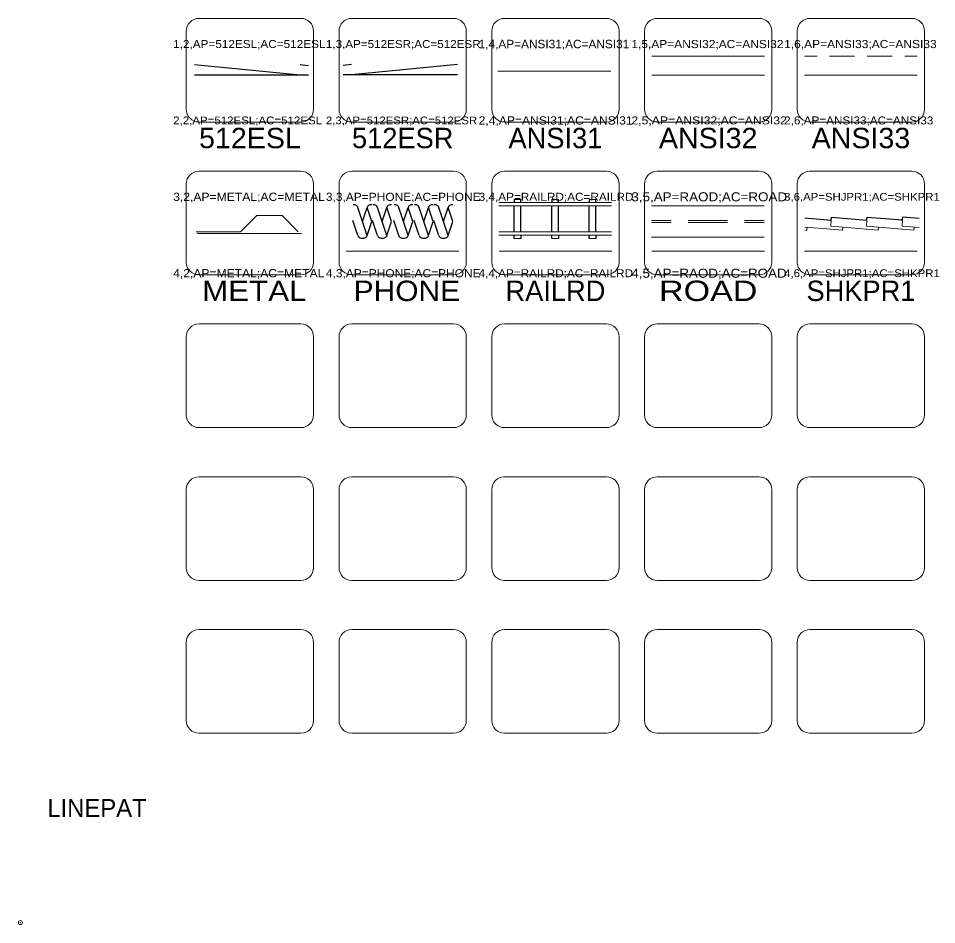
# Model space of a CAD drawing. Extents: x 95935 to 95946.4, y 95971.2 to 95974.7.
# Drawn here: x 95935.026 to 95938.633, y 95971.173 to 95974.732 of the extents above; entities that cross this region are included whole.
import ezdxf
from ezdxf.enums import TextEntityAlignment as Align

# ---------------------------------------------------------------- set-up
doc = ezdxf.new("R2010")
doc.units = 0
doc.header["$LTSCALE"] = 0.032
doc.header["$PDMODE"] = 32
doc.header["$PDSIZE"] = 0.016
for name, color, linetype, lineweight in [('1', 7, 'Continuous', 13), ('25', 7, 'Continuous', 13), ('6', 7, 'Continuous', 13), ('63', 7, 'Continuous', 13)]:
    doc.layers.add(name, color=color, linetype=linetype, lineweight=lineweight)
doc.layers.add('20', color=7, linetype='Continuous')

msp = doc.modelspace()

# ---------------------------------------------------------------- linework, layer by layer
at = {"layer": '1'}
for p, q in [((95935.7357, 95974.7318), (95936.1357, 95974.7318)), ((95936.3357, 95974.7318), (95936.7357, 95974.7318)), ((95936.9357, 95974.7318), (95937.3357, 95974.7318)), ((95937.5357, 95974.7318), (95937.9357, 95974.7318)), ((95938.1357, 95974.7318), (95938.5357, 95974.7318)), ((95935.6857, 95974.3747), (95935.6857, 95974.6818)), ((95936.1857, 95974.6818), (95936.1857, 95974.3747)), ((95936.2857, 95974.3747), (95936.2857, 95974.6818)), ((95936.7857, 95974.6818), (95936.7857, 95974.3747)), ((95936.8857, 95974.3747), (95936.8857, 95974.6818)), ((95937.3857, 95974.6818), (95937.3857, 95974.3747)), ((95937.4857, 95974.3747), (95937.4857, 95974.6818)), ((95937.9857, 95974.6818), (95937.9857, 95974.3747)), ((95938.0857, 95974.3747), (95938.0857, 95974.6818)), ((95938.5857, 95974.6818), (95938.5857, 95974.3747)), ((95936.1357, 95974.3247), (95935.7357, 95974.3247)), ((95936.7357, 95974.3247), (95936.3357, 95974.3247)), ((95937.3357, 95974.3247), (95936.9357, 95974.3247)), ((95937.9357, 95974.3247), (95937.5357, 95974.3247)), ((95938.5357, 95974.3247), (95938.1357, 95974.3247)), ((95935.7357, 95974.1318), (95936.1357, 95974.1318)), ((95936.3357, 95974.1318), (95936.7357, 95974.1318)), ((95936.9357, 95974.1318), (95937.3357, 95974.1318)), ((95937.5357, 95974.1318), (95937.9357, 95974.1318)), ((95938.1357, 95974.1318), (95938.5357, 95974.1318)), ((95935.6857, 95973.7747), (95935.6857, 95974.0818)), ((95936.1857, 95974.0818), (95936.1857, 95973.7747)), ((95936.2857, 95973.7747), (95936.2857, 95974.0818)), ((95936.7857, 95974.0818), (95936.7857, 95973.7747)), ((95936.8857, 95973.7747), (95936.8857, 95974.0818)), ((95937.3857, 95974.0818), (95937.3857, 95973.7747)), ((95937.4857, 95973.7747), (95937.4857, 95974.0818)), ((95937.9857, 95974.0818), (95937.9857, 95973.7747)), ((95938.0857, 95973.7747), (95938.0857, 95974.0818)), ((95938.5857, 95974.0818), (95938.5857, 95973.7747)), ((95936.1357, 95973.7247), (95935.7357, 95973.7247)), ((95936.7357, 95973.7247), (95936.3357, 95973.7247)), ((95937.3357, 95973.7247), (95936.9357, 95973.7247)), ((95937.9357, 95973.7247), (95937.5357, 95973.7247)), ((95938.5357, 95973.7247), (95938.1357, 95973.7247)), ((95935.7357, 95973.5318), (95936.1357, 95973.5318)), ((95936.3357, 95973.5318), (95936.7357, 95973.5318)), ((95936.9357, 95973.5318), (95937.3357, 95973.5318)), ((95937.5357, 95973.5318), (95937.9357, 95973.5318)), ((95938.1357, 95973.5318), (95938.5357, 95973.5318)), ((95935.6857, 95973.1747), (95935.6857, 95973.4818)), ((95936.1857, 95973.4818), (95936.1857, 95973.1747)), ((95936.2857, 95973.1747), (95936.2857, 95973.4818)), ((95936.7857, 95973.4818), (95936.7857, 95973.1747)), ((95936.8857, 95973.1747), (95936.8857, 95973.4818)), ((95937.3857, 95973.4818), (95937.3857, 95973.1747)), ((95937.4857, 95973.1747), (95937.4857, 95973.4818)), ((95937.9857, 95973.4818), (95937.9857, 95973.1747)), ((95938.0857, 95973.1747), (95938.0857, 95973.4818)), ((95938.5857, 95973.4818), (95938.5857, 95973.1747)), ((95936.1357, 95973.1247), (95935.7357, 95973.1247)), ((95936.7357, 95973.1247), (95936.3357, 95973.1247)), ((95937.3357, 95973.1247), (95936.9357, 95973.1247)), ((95937.9357, 95973.1247), (95937.5357, 95973.1247)), ((95938.5357, 95973.1247), (95938.1357, 95973.1247)), ((95935.7357, 95972.9318), (95936.1357, 95972.9318)), ((95936.3357, 95972.9318), (95936.7357, 95972.9318)), ((95936.9357, 95972.9318), (95937.3357, 95972.9318)), ((95937.5357, 95972.9318), (95937.9357, 95972.9318)), ((95938.1357, 95972.9318), (95938.5357, 95972.9318)), ((95935.6857, 95972.5747), (95935.6857, 95972.8818)), ((95936.1857, 95972.8818), (95936.1857, 95972.5747)), ((95936.2857, 95972.5747), (95936.2857, 95972.8818)), ((95936.7857, 95972.8818), (95936.7857, 95972.5747)), ((95936.8857, 95972.5747), (95936.8857, 95972.8818)), ((95937.3857, 95972.8818), (95937.3857, 95972.5747)), ((95937.4857, 95972.5747), (95937.4857, 95972.8818)), ((95937.9857, 95972.8818), (95937.9857, 95972.5747)), ((95938.0857, 95972.5747), (95938.0857, 95972.8818)), ((95938.5857, 95972.8818), (95938.5857, 95972.5747)), ((95936.1357, 95972.5247), (95935.7357, 95972.5247)), ((95936.7357, 95972.5247), (95936.3357, 95972.5247)), ((95937.3357, 95972.5247), (95936.9357, 95972.5247)), ((95937.9357, 95972.5247), (95937.5357, 95972.5247)), ((95938.5357, 95972.5247), (95938.1357, 95972.5247)), ((95935.7357, 95972.3318), (95936.1357, 95972.3318)), ((95936.3357, 95972.3318), (95936.7357, 95972.3318)), ((95936.9357, 95972.3318), (95937.3357, 95972.3318)), ((95937.5357, 95972.3318), (95937.9357, 95972.3318)), ((95938.1357, 95972.3318), (95938.5357, 95972.3318)), ((95935.6857, 95971.9747), (95935.6857, 95972.2818)), ((95936.1857, 95972.2818), (95936.1857, 95971.9747)), ((95936.2857, 95971.9747), (95936.2857, 95972.2818)), ((95936.7857, 95972.2818), (95936.7857, 95971.9747)), ((95936.8857, 95971.9747), (95936.8857, 95972.2818)), ((95937.3857, 95972.2818), (95937.3857, 95971.9747)), ((95937.4857, 95971.9747), (95937.4857, 95972.2818)), ((95937.9857, 95972.2818), (95937.9857, 95971.9747)), ((95938.0857, 95971.9747), (95938.0857, 95972.2818)), ((95938.5857, 95972.2818), (95938.5857, 95971.9747)), ((95936.1357, 95971.9247), (95935.7357, 95971.9247)), ((95936.7357, 95971.9247), (95936.3357, 95971.9247)), ((95937.3357, 95971.9247), (95936.9357, 95971.9247)), ((95937.9357, 95971.9247), (95937.5357, 95971.9247)), ((95938.5357, 95971.9247), (95938.1357, 95971.9247))]:
    msp.add_line(p, q, dxfattribs=at)
for centre, start, end in [((95935.7357, 95974.6818), 90, 180), ((95936.1357, 95974.6818), 0, 90), ((95936.3357, 95974.6818), 90, 180), ((95936.7357, 95974.6818), 0, 90), ((95936.9357, 95974.6818), 90, 180), ((95937.3357, 95974.6818), 0, 90), ((95937.5357, 95974.6818), 90, 180), ((95937.9357, 95974.6818), 0, 90), ((95938.1357, 95974.6818), 90, 180), ((95938.5357, 95974.6818), 0, 90), ((95935.7357, 95974.3747), 180, 270), ((95936.1357, 95974.3747), 270, 0), ((95936.3357, 95974.3747), 180, 270), ((95936.7357, 95974.3747), 270, 0), ((95936.9357, 95974.3747), 180, 270), ((95937.3357, 95974.3747), 270, 0), ((95937.5357, 95974.3747), 180, 270), ((95937.9357, 95974.3747), 270, 0), ((95938.1357, 95974.3747), 180, 270), ((95938.5357, 95974.3747), 270, 0), ((95935.7357, 95974.0818), 90, 180), ((95936.1357, 95974.0818), 0, 90), ((95936.3357, 95974.0818), 90, 180), ((95936.7357, 95974.0818), 0, 90), ((95936.9357, 95974.0818), 90, 180), ((95937.3357, 95974.0818), 0, 90), ((95937.5357, 95974.0818), 90, 180), ((95937.9357, 95974.0818), 0, 90), ((95938.1357, 95974.0818), 90, 180), ((95938.5357, 95974.0818), 0, 90), ((95935.7357, 95973.7747), 180, 270), ((95936.1357, 95973.7747), 270, 0), ((95936.3357, 95973.7747), 180, 270), ((95936.7357, 95973.7747), 270, 0), ((95936.9357, 95973.7747), 180, 270), ((95937.3357, 95973.7747), 270, 0), ((95937.5357, 95973.7747), 180, 270), ((95937.9357, 95973.7747), 270, 0), ((95938.1357, 95973.7747), 180, 270), ((95938.5357, 95973.7747), 270, 0), ((95935.7357, 95973.4818), 90, 180), ((95936.1357, 95973.4818), 0, 90), ((95936.3357, 95973.4818), 90, 180), ((95936.7357, 95973.4818), 0, 90), ((95936.9357, 95973.4818), 90, 180), ((95937.3357, 95973.4818), 0, 90), ((95937.5357, 95973.4818), 90, 180), ((95937.9357, 95973.4818), 0, 90), ((95938.1357, 95973.4818), 90, 180), ((95938.5357, 95973.4818), 0, 90), ((95935.7357, 95973.1747), 180, 270), ((95936.1357, 95973.1747), 270, 0), ((95936.3357, 95973.1747), 180, 270), ((95936.7357, 95973.1747), 270, 0), ((95936.9357, 95973.1747), 180, 270), ((95937.3357, 95973.1747), 270, 0), ((95937.5357, 95973.1747), 180, 270), ((95937.9357, 95973.1747), 270, 0), ((95938.1357, 95973.1747), 180, 270), ((95938.5357, 95973.1747), 270, 0), ((95935.7357, 95972.8818), 90, 180), ((95936.1357, 95972.8818), 0, 90), ((95936.3357, 95972.8818), 90, 180), ((95936.7357, 95972.8818), 0, 90), ((95936.9357, 95972.8818), 90, 180), ((95937.3357, 95972.8818), 0, 90), ((95937.5357, 95972.8818), 90, 180), ((95937.9357, 95972.8818), 0, 90), ((95938.1357, 95972.8818), 90, 180), ((95938.5357, 95972.8818), 0, 90), ((95935.7357, 95972.5747), 180, 270), ((95936.1357, 95972.5747), 270, 0), ((95936.3357, 95972.5747), 180, 270), ((95936.7357, 95972.5747), 270, 0), ((95936.9357, 95972.5747), 180, 270), ((95937.3357, 95972.5747), 270, 0), ((95937.5357, 95972.5747), 180, 270), ((95937.9357, 95972.5747), 270, 0), ((95938.1357, 95972.5747), 180, 270), ((95938.5357, 95972.5747), 270, 0), ((95935.7357, 95972.2818), 90, 180), ((95936.1357, 95972.2818), 0, 90), ((95936.3357, 95972.2818), 90, 180), ((95936.7357, 95972.2818), 0, 90), ((95936.9357, 95972.2818), 90, 180), ((95937.3357, 95972.2818), 0, 90), ((95937.5357, 95972.2818), 90, 180), ((95937.9357, 95972.2818), 0, 90), ((95938.1357, 95972.2818), 90, 180), ((95938.5357, 95972.2818), 0, 90), ((95935.7357, 95971.9747), 180, 270), ((95936.1357, 95971.9747), 270, 0), ((95936.3357, 95971.9747), 180, 270), ((95936.7357, 95971.9747), 270, 0), ((95936.9357, 95971.9747), 180, 270), ((95937.3357, 95971.9747), 270, 0), ((95937.5357, 95971.9747), 180, 270), ((95937.9357, 95971.9747), 270, 0), ((95938.1357, 95971.9747), 180, 270), ((95938.5357, 95971.9747), 270, 0)]:
    msp.add_arc(centre, 0.05, start, end, dxfattribs=at)
at = {"layer": '25'}
for p, q in [((95935.7278, 95973.8875), (95936.1378, 95973.8875)), ((95937.3569, 95973.8178), (95936.9141, 95973.8178)), ((95937.9569, 95973.8178), (95937.5141, 95973.8178)), ((95938.5569, 95973.8178), (95938.1141, 95973.8178))]:
    msp.add_line(p, q, dxfattribs=at)
at = {"layer": '6'}
for p, q in [((95937.5141, 95974.5836), (95937.9569, 95974.5836)), ((95938.1141, 95974.5836), (95938.1633, 95974.5836)), ((95938.2125, 95974.5836), (95938.3109, 95974.5836)), ((95938.3601, 95974.5836), (95938.4585, 95974.5836)), ((95938.5077, 95974.5836), (95938.5569, 95974.5836)), ((95936.9101, 95974.5244), (95937.3529, 95974.5244)), ((95937.5141, 95974.5086), (95937.9569, 95974.5086)), ((95938.1141, 95974.5086), (95938.5569, 95974.5086)), ((95936.9128, 95974.0083), (95937.3556, 95974.0083)), ((95936.9128, 95973.9955), (95937.3556, 95973.9955)), ((95936.9736, 95974.021), (95936.9999, 95974.021)), ((95937.1212, 95974.021), (95937.1475, 95974.021)), ((95937.2688, 95974.021), (95937.2951, 95974.021)), ((95937.5127, 95973.9951), (95937.9555, 95973.9951)), ((95937.5127, 95973.9375), (95937.5902, 95973.9375)), ((95937.5127, 95973.9299), (95937.5902, 95973.9299)), ((95937.6566, 95973.9375), (95937.8116, 95973.9375)), ((95937.6566, 95973.9299), (95937.8116, 95973.9299)), ((95937.878, 95973.9375), (95937.9555, 95973.9375)), ((95937.878, 95973.9299), (95937.9555, 95973.9299)), ((95938.2192, 95973.9395), (95938.2172, 95973.9155)), ((95938.3592, 95973.9398), (95938.3572, 95973.9158)), ((95938.4992, 95973.9401), (95938.4972, 95973.9161)), ((95936.9128, 95973.8931), (95937.3556, 95973.8931)), ((95938.1154, 95973.912), (95938.2192, 95973.9034)), ((95938.1154, 95973.9001), (95938.1239, 95973.8994)), ((95938.1249, 95973.9113), (95938.1239, 95973.8994)), ((95938.2152, 95973.9037), (95938.2639, 95973.8997)), ((95938.2172, 95973.9155), (95938.3592, 95973.9037)), ((95938.2649, 95973.9116), (95938.2639, 95973.8997)), ((95938.3552, 95973.904), (95938.4039, 95973.9)), ((95938.3572, 95973.9158), (95938.4992, 95973.904)), ((95938.4049, 95973.9119), (95938.4039, 95973.9)), ((95938.4952, 95973.9043), (95938.5439, 95973.9003)), ((95938.4972, 95973.9161), (95938.5641, 95973.9105)), ((95938.5449, 95973.9122), (95938.5439, 95973.9003)), ((95936.9128, 95973.8803), (95937.3556, 95973.8803)), ((95936.9736, 95973.8675), (95936.9999, 95973.8675)), ((95937.1212, 95973.8675), (95937.1475, 95973.8675)), ((95937.2688, 95973.8675), (95937.2951, 95973.8675)), ((95937.5127, 95973.8723), (95937.9555, 95973.8723))]:
    msp.add_line(p, q, dxfattribs=at)
at = {"layer": '6', "lineweight": 25}
for p, q in [((95935.7175, 95974.5504), (95936.1335, 95974.5104)), ((95936.1335, 95974.5504), (95936.1663, 95974.5472)), ((95936.3347, 95974.5504), (95936.3019, 95974.5472)), ((95936.7507, 95974.5504), (95936.3347, 95974.5104)), ((95935.7175, 95974.5104), (95936.1663, 95974.5104)), ((95936.7507, 95974.5104), (95936.3019, 95974.5104)), ((95936.9736, 95974.021), (95936.9736, 95974.0082)), ((95936.9736, 95973.8931), (95936.9736, 95973.9955)), ((95936.9999, 95974.0082), (95936.9999, 95974.021)), ((95936.9999, 95973.8931), (95936.9999, 95973.9955)), ((95937.1212, 95974.021), (95937.1212, 95974.0082)), ((95937.1212, 95973.8931), (95937.1212, 95973.9955)), ((95937.1475, 95974.0082), (95937.1475, 95974.021)), ((95937.1475, 95973.8931), (95937.1475, 95973.9955)), ((95937.2688, 95974.021), (95937.2688, 95974.0082)), ((95937.2688, 95973.8931), (95937.2688, 95973.9955)), ((95937.2951, 95974.0082), (95937.2951, 95974.021)), ((95937.2951, 95973.8931), (95937.2951, 95973.9955)), ((95936.3961, 95973.8798), (95936.3596, 95973.9895)), ((95936.3779, 95973.9346), (95936.3961, 95973.9892)), ((95936.4144, 95973.9345), (95936.3961, 95973.9895)), ((95936.4735, 95973.8798), (95936.437, 95973.9895)), ((95936.4553, 95973.9346), (95936.4735, 95973.9892)), ((95936.4918, 95973.9345), (95936.4735, 95973.9895)), ((95936.5568, 95973.8798), (95936.5203, 95973.9895)), ((95936.5386, 95973.9346), (95936.5568, 95973.9892)), ((95936.5751, 95973.9345), (95936.5568, 95973.9895)), ((95936.6372, 95973.8798), (95936.6007, 95973.9895)), ((95936.619, 95973.9346), (95936.6372, 95973.9892)), ((95936.6555, 95973.9345), (95936.6372, 95973.9895)), ((95936.7145, 95973.8798), (95936.678, 95973.9895)), ((95936.6963, 95973.9346), (95936.7145, 95973.9892)), ((95936.7328, 95973.9345), (95936.7145, 95973.9895)), ((95936.3596, 95973.8798), (95936.3403, 95973.9378)), ((95936.3961, 95973.8798), (95936.4143, 95973.9345)), ((95936.437, 95973.8798), (95936.4177, 95973.9378)), ((95936.4735, 95973.8798), (95936.4917, 95973.9345)), ((95936.5203, 95973.8798), (95936.501, 95973.9378)), ((95936.5568, 95973.8798), (95936.575, 95973.9345)), ((95936.6007, 95973.8798), (95936.5814, 95973.9378)), ((95936.6372, 95973.8798), (95936.6554, 95973.9345)), ((95936.678, 95973.8798), (95936.6587, 95973.9378)), ((95936.7145, 95973.8798), (95936.7327, 95973.9345)), ((95938.1154, 95973.9482), (95938.2192, 95973.9395)), ((95938.2152, 95973.9398), (95938.2192, 95973.9395)), ((95938.2192, 95973.9395), (95938.2202, 95973.9514)), ((95938.2202, 95973.9514), (95938.3592, 95973.9398)), ((95938.3552, 95973.9401), (95938.3592, 95973.9398)), ((95938.3592, 95973.9398), (95938.3602, 95973.9517)), ((95938.3602, 95973.9517), (95938.4992, 95973.9401)), ((95938.4952, 95973.9404), (95938.4992, 95973.9401)), ((95938.4992, 95973.9401), (95938.5002, 95973.952)), ((95938.5002, 95973.952), (95938.5641, 95973.9467)), ((95936.9736, 95973.8675), (95936.9736, 95973.8803)), ((95936.9999, 95973.8803), (95936.9999, 95973.8675)), ((95937.1212, 95973.8675), (95937.1212, 95973.8803)), ((95937.1475, 95973.8803), (95937.1475, 95973.8675)), ((95937.2688, 95973.8675), (95937.2688, 95973.8803)), ((95937.2951, 95973.8803), (95937.2951, 95973.8675))]:
    msp.add_line(p, q, dxfattribs=at)
at = {"layer": '6'}
msp.add_lwpolyline([(95935.7242, 95973.8941), (95935.8993, 95973.8941), (95935.9623, 95973.9571), (95936.0624, 95973.9571), (95936.1258, 95973.8936)], dxfattribs=at)
at = {"layer": '6', "lineweight": 25}
for centre, start_param, end_param in [((95936.3414, 95973.9892), 3.141593, 4.712389), ((95936.4143, 95973.9892), 4.712389, 6.283185), ((95936.4188, 95973.9892), 3.141593, 4.712389), ((95936.4917, 95973.9892), 4.712389, 6.283185), ((95936.5021, 95973.9892), 3.141593, 4.712389), ((95936.575, 95973.9892), 4.712389, 6.283185), ((95936.5825, 95973.9892), 3.141593, 4.712389), ((95936.6554, 95973.9892), 4.712389, 6.283185), ((95936.6598, 95973.9892), 3.141593, 4.712389), ((95936.7327, 95973.9892), 4.712389, 6.283185), ((95936.3779, 95973.8798), 6.283185, 9.424778), ((95936.4553, 95973.8798), 6.283185, 9.424778), ((95936.5386, 95973.8798), 6.283185, 9.424778), ((95936.619, 95973.8798), 6.283185, 9.424778), ((95936.6963, 95973.8798), 6.283185, 9.424778)]:
    msp.add_ellipse(centre, major_axis=(-0.0182, 0), ratio=0.6, start_param=start_param, end_param=end_param, dxfattribs=at)
at = {"layer": '63'}
msp.add_line((95936.7569, 95973.8178), (95936.3141, 95973.8178), dxfattribs=at)
msp.add_point((95935.0341, 95971.1811), dxfattribs=at)

# ---------------------------------------------------------------- texts
at = {"layer": '20'}
for s, width, p in [('512ESL', 1.05, (95935.9358, 95974.222)), ('ANSI32', 1.05, (95937.7357, 95974.222)), ('ANSI33', 1.05, (95938.3359, 95974.222)), (' PHONE', 1.1, (95936.5359, 95973.622)), (' ROAD ', 1.25, (95937.7358, 95973.622)), (' METAL', 1.15, (95935.9358, 95973.622))]:
    msp.add_text(s, height=0.08, dxfattribs=dict(at, width=width)).set_placement(p, align=Align.CENTER)
for s, p in [('512ESR', (95936.5358, 95974.222)), ('ANSI31', (95937.1357, 95974.222)), ('SHKPR1', (95938.3359, 95973.622)), ('RAILRD', (95937.1358, 95973.622))]:
    msp.add_text(s, height=0.08, dxfattribs=at).set_placement(p, align=Align.CENTER)
at = {"layer": '6'}
msp.add_text('LINEPAT', height=0.07, dxfattribs=at).set_placement((95935.335, 95971.5961), align=Align.CENTER)
at = {"layer": '63'}
for s, height, width, p in [('1,2,AP=512ESL;AC=512ESL', 0.0314, 1.1, (95935.6341, 95974.6154)), ('1,3,AP=512ESR;AC=512ESR', 0.0311, 1.1, (95936.2341, 95974.6155)), ('1,4,AP=ANSI31;AC=ANSI31', 0.0331, 1.05, (95936.8341, 95974.6145)), ('1,5,AP=ANSI32;AC=ANSI32', 0.0319, 1.1, (95937.4341, 95974.6151)), ('1,6,AP=ANSI33;AC=ANSI33', 0.032, 1.1, (95938.0341, 95974.6151)), ('2,2,AP=512ESL;AC=512ESL', 0.0307, 1.1, (95935.6341, 95974.3157)), ('2,3,AP=512ESR;AC=512ESR', 0.0304, 1.1, (95936.2341, 95974.3159)), ('2,4,AP=ANSI31;AC=ANSI31', 0.0323, 1.1, (95936.8341, 95974.3149)), ('2,5,AP=ANSI32;AC=ANSI32', 0.0312, 1.15, (95937.4341, 95974.3155)), ('2,6,AP=ANSI33;AC=ANSI33', 0.0313, 1.1, (95938.0341, 95974.3154)), ('3,2,AP=METAL;AC=METAL', 0.0324, 1.1, (95935.6341, 95974.0149)), ('3,3,AP=PHONE;AC=PHONE', 0.0319, 1.1, (95936.2341, 95974.0151)), ('3,4,AP=RAILRD;AC=RAILRD', 0.0314, 1.1, (95936.8341, 95974.0154)), ('3,5,AP=RAOD;AC=ROAD', 0.0358, 1.1, (95937.4341, 95974.0132)), ('3,6,AP=SHJPR1;AC=SHKPR1', 0.0304, 1.1, (95938.0341, 95974.0159)), ('4,2,AP=METAL;AC=METAL', 0.0323, 1.1, (95935.6341, 95973.7149)), ('4,3,AP=PHONE;AC=PHONE', 0.0319, 1.1, (95936.2341, 95973.7151)), ('4,4,AP=RAILRD;AC=RAILRD', 0.0313, 1.1, (95936.8341, 95973.7154)), ('4,5,AP=RAOD;AC=ROAD', 0.0357, 1.1, (95937.4341, 95973.7132)), ('4,6,AP=SHJPR1;AC=SHKPR1', 0.0304, 1.1, (95938.0341, 95973.7159))]:
    msp.add_text(s, height=height, dxfattribs=dict(at, width=width)).set_placement(p)

doc.saveas('drawing.dxf')
